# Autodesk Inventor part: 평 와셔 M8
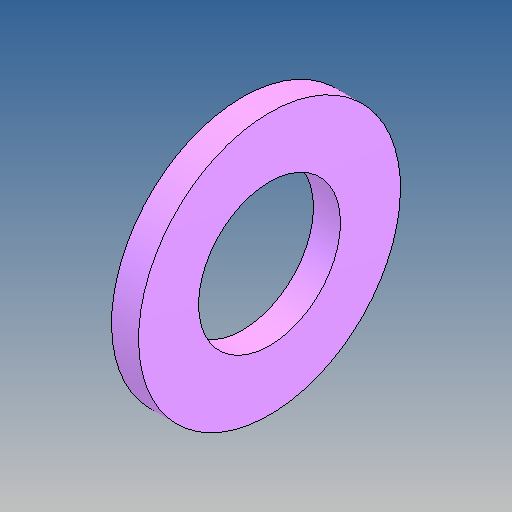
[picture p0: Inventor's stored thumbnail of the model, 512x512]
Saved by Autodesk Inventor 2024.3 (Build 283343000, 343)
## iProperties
Created: 2025-06
Part Number: 평 와셔 M8
Material: 강철, 연강
Description: 평면 와셔
Document SubType Name: Modeling
Designer: user
Density: 7.85 g/cm^3
Appearance: 기본값
Author: jhkim
Sending System: Autodesk Inventor 2026
Preprocessor: ST-DEVELOPER v20.1
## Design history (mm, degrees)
node "평 와셔 M81"
node "솔리드1"
body "Solid1"
